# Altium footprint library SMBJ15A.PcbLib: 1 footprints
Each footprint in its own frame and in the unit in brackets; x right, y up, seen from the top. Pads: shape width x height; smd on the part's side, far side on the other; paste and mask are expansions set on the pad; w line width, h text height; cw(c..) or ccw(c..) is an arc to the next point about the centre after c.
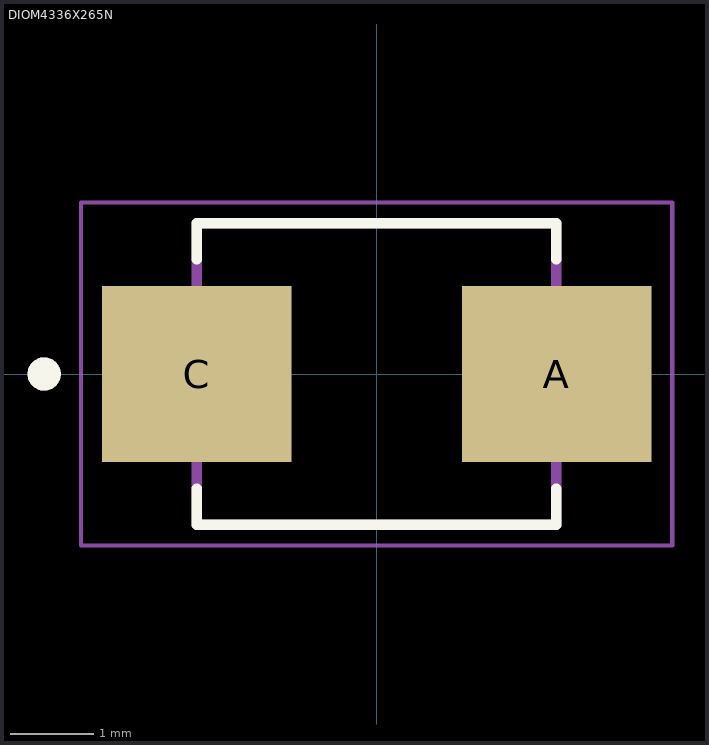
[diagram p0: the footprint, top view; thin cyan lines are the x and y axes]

## DIOM4336X265N [mm]
height 2.65
pads (2):
  rect 2.28x2.12 smd paste+0 mask+0.102: A(2.165,0) C(-2.165,0)
Top Overlay:
  circle w0.2: c-4,0 r0.1
  lines w0.127: -2.163,-1.38 -2.163,-1.813 2.163,-1.813 2.163,-1.38 ; -2.163,1.38 -2.163,1.813 2.163,1.813 2.163,1.38
Assembly Top:
  circle w0.2: c-4,0 r0.1
  lines w0.127: -2.163,-1.813 -2.163,1.813 2.163,1.813 2.163,-1.813 -2.163,-1.813
Courtyard Top:
  lines w0.05: -3.555,-2.063 -3.555,2.063 3.555,2.063 3.555,-2.063 -3.555,-2.063
3D body "step_temp.STEP": height 2.25, standoff -1.45, extent 2.297,-2.575 7.697,-0.375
